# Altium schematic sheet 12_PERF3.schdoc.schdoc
size 302 x 215 mm; Symbol: Sheet_A4; Device: Sheet_A4; @Project Name: Avaota Pi A; Company: YuzukiHD; Version: 1.0; @Page No: 10; @Page Count: 13; @Update Date: 2024-02-27; Comment: GloomyGhost
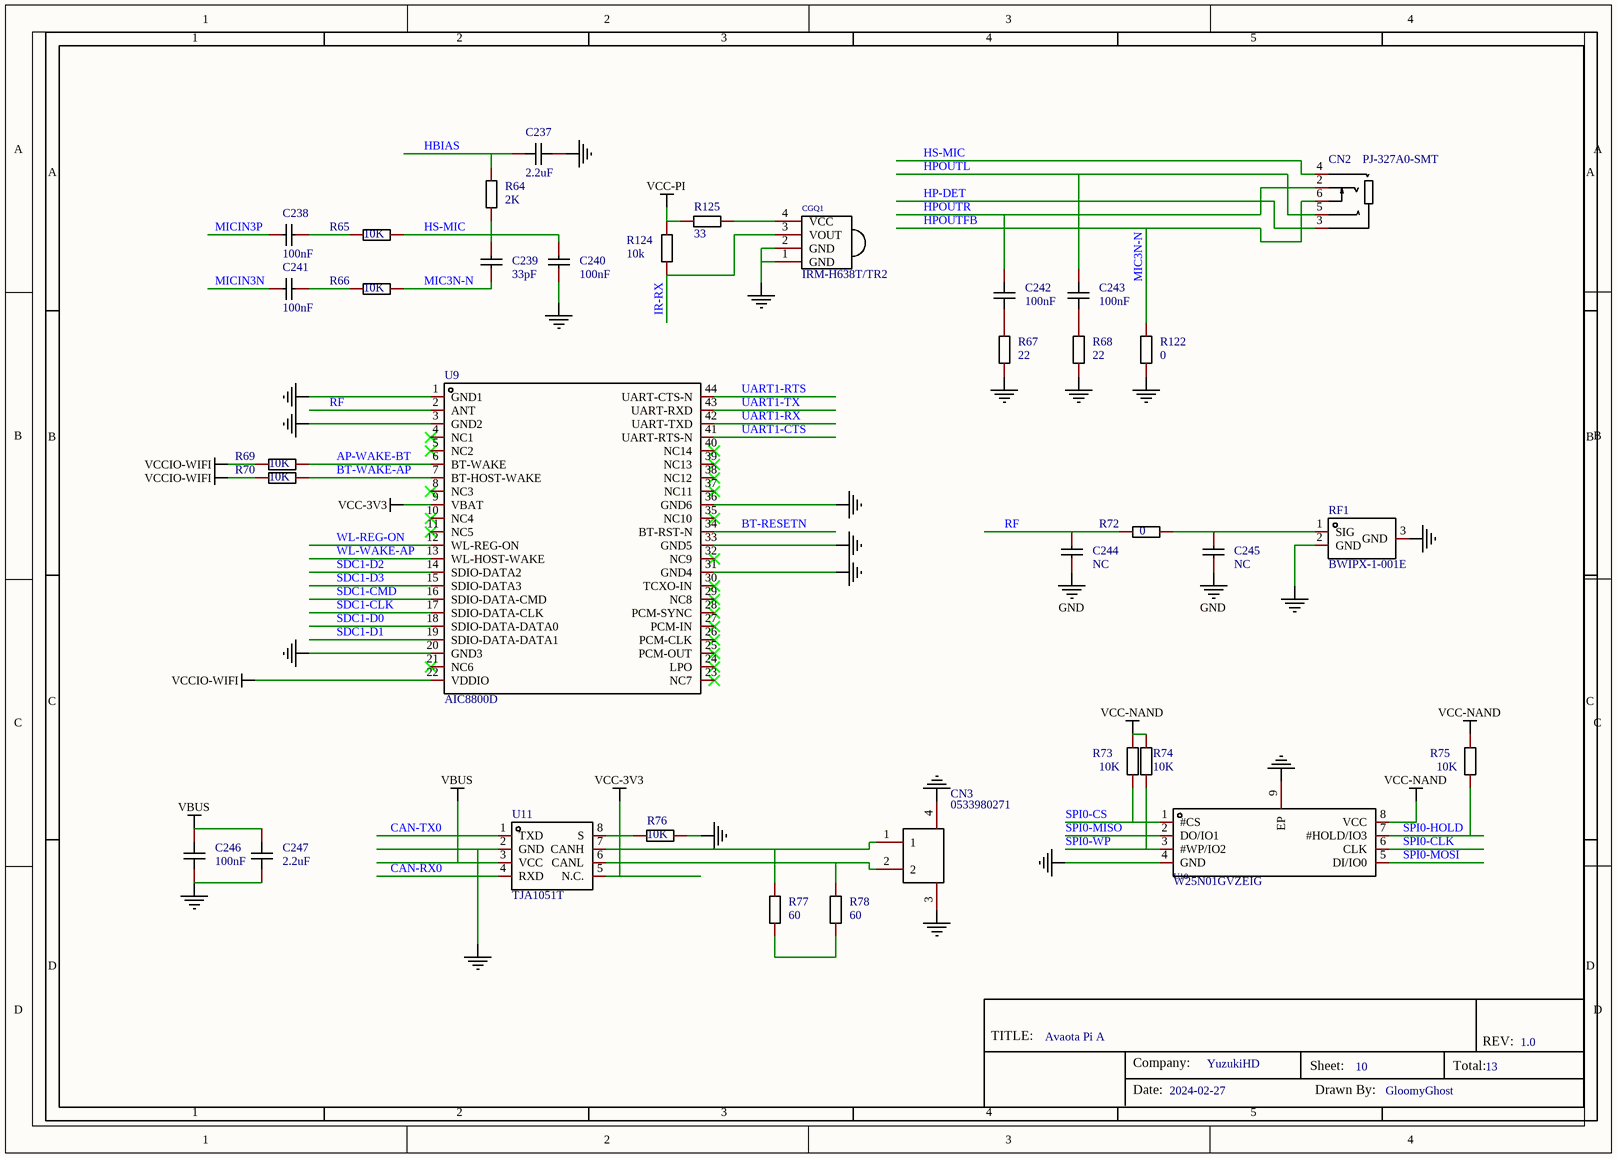
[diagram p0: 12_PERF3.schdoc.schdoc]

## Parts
C237  2.2uF  [c0402-nsk]
C238  100nF  [c0201 nsk]
C239  33pF  [c0201 nsk]
C240  100nF  [c0201 nsk]
C241  100nF  [c0201 nsk]
C242  100nF  [c0402-nsk]
C243  100nF  [c0402-nsk]
C244  NC  [c0201 nsk]
C245  NC  [c0201 nsk]
C246  100nF  [c0402-nsk]
C247  2.2uF  [c0402-nsk]
CGQ1  IRM-H638T/TR2  [SENSOR-SMD_IRM-H638T-TR2-TL]
CN2  PJ-327A0-SMT  [AUDIO-SMD_PJ-327A0-SMT]
CN3  0533980271  [CONN-SMD_2P-P1.25_053398-0X71]
R64  2K  [r0201 nsk]
R65  10K  [r0201 nsk]
R66  10K  [r0201 nsk]
R67  22  [r0201 nsk]
R68  22  [r0201 nsk]
R69  10K  [r0201 nsk]
R70  10K  [r0201 nsk]
R72  0  [r0201 nsk]
R73  10K  [r0201 nsk]
R74  10K  [r0201 nsk]
R75  10K  [r0201 nsk]
R76  10K  [r0201 nsk]
R77  60  [r0201 nsk]
R78  60  [r0201 nsk]
R122  0  [r0201 nsk]
R124  10k  [r0201 nsk]
R125  33  [r0201 nsk]
RF1  BWIPX-1-001E  [IPEX-SMD_BWIPX-1-001E]
U9  AIC8800D  [LGA-44_L12.0-W12.0-P0.90]
U11  TJA1051T  [SOP-8_L4.9-W3.9-P1.27-LS6.0-BL]
U18  W25N01GVZEIG  [WSON-8_L8.0-W6.10-P1.27-BL-EP]

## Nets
GND: C244.1 C245.1 U18.4(GND)
NetC237_1: C237.1 C240.1 C246.1 C247.1 CGQ1.1(GND) CGQ1.2(GND) CN3.3 CN3.4 R67.1 R68.1 R76.2 R122.1 RF1.2(GND) RF1.3(GND) U9.1(GND1) U9.3(GND2) U9.20(GND3) U9.31(GND4) U9.33(GND5) U9.36(GND6) U11.2(GND) U18.9(EP)
VBUS: C246.2 C247.2 U11.3(VCC)
VCC-3V3: U9.9(VBAT) U11.5(N.C.)
VCC-NAND: R73.2 R74.2 R75.2 U18.8(VCC)
VCC-PI: R124.2 R125.2
VCCIO-WIFI: R69.1 R70.1 U9.22(VDDIO)
AP-WAKE-BT: R69.2 U9.6(BT-WAKE)
BT-RESETN: U9.34(BT-RST-N)
BT-WAKE-AP: R70.2 U9.7(BT-HOST-WAKE)
CAN-RX0: U11.4(RXD)
CAN-TX0: U11.1(TXD)
HBIAS: C237.2 R64.2
HP-DET: CN2.3
HPOUTFB: C239.1 CN2.6 R66.2 R122.2  [also labelled MIC3N-N]
HPOUTL: C243.1 CN2.5
HPOUTR: C242.1 CN2.2
HS-MIC: C239.2 C240.2 CN2.4 R64.1 R65.2
IR-RX: CGQ1.3(VOUT) R124.1
MICIN3N: C241.1
MICIN3P: C238.1
RF: C244.2 R72.1 U9.2(ANT)
SDC1-CLK: U9.17(SDIO-DATA-CLK)
SDC1-CMD: U9.16(SDIO-DATA-CMD)
SDC1-D0: U9.18(SDIO-DATA-DATA0)
SDC1-D1: U9.19(SDIO-DATA-DATA1)
SDC1-D2: U9.14(SDIO-DATA2)
SDC1-D3: U9.15(SDIO-DATA3)
SPI0-CLK: U18.6(CLK)
SPI0-CS: R73.1 U18.1(#CS)
SPI0-HOLD: R75.1 U18.7(#HOLD/IO3)
SPI0-MISO: U18.2(DO/IO1)
SPI0-MOSI: U18.5(DI/IO0)
SPI0-WP: R74.1 U18.3(#WP/IO2)
UART1-CTS: U9.41(UART-RTS-N)
UART1-RTS: U9.44(UART-CTS-N)
UART1-RX: U9.42(UART-TXD)
UART1-TX: U9.43(UART-RXD)
WL-REG-ON: U9.12(WL-REG-ON)
WL-WAKE-AP: U9.13(WL-HOST-WAKE)
NetC238_2: C238.2 R65.1
NetC241_2: C241.2 R66.1
NetC242_2: C242.2 R67.2
NetC243_2: C243.2 R68.2
NetC245_2: C245.2 R72.2 RF1.1(SIG)
NetCGQ1_4: CGQ1.4(VCC) R125.1
NetCN3_1: CN3.1 R77.2 U11.7(CANH)
NetCN3_2: CN3.2 R78.2 U11.6(CANL)
NetR76_1: R76.1 U11.8(S)
NetR77_1: R77.1 R78.1

Not connected (* = marked no-connect by the designer): U9 4(NC1)* 5(NC2)* 8(NC3)* 10(NC4)* 11(NC5)* 21(NC6)* 23(NC7)* 24(LPO)* 25(PCM-OUT)* 26(PCM-CLK)* 27(PCM-IN)* 28(PCM-SYNC)* 29(NC8)* 30(TCXO-IN)* 32(NC9)* 35(NC10)* 37(NC11)* 38(NC12)* 39(NC13)* 40(NC14)*

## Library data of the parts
C237 C242 C243 C246 C247 = CAP_0402: Symbol: CapAcitance; Convert to PCB: yes
C238-C241 C244 C245 = GRM033R61A104KE15D: Manufacturer: muRata(村田); Add into BOM: yes; Tolerance: ±10%; Voltage Rated: 10V; Temperature Coefficient: X5R; Description: 容值:100nF;精度:±10%;额定电压:10V;材质(温度系数):X5R;
CGQ1 = IRM-H638T/TR2: Manufacturer: EVERLIGHT(亿光); Add into BOM: yes; Supply Voltage: 2.7V~5.5V; Supply Current: 1.2mA; Description: 工作电压:2.7V~5.5V;工作电流:1.2mA;接收距离:-;中心频率:-;接收角度:-;
CN2 = PJ-327A0-SMT: Manufacturer: XKB Connectivity(中国星坤); Add into BOM: yes; Connector Type: 3.5mm耳机座; Current Rating (Max): 500mA; Voltage Rating (Max): 30V; Soldering Temperature(Max): 235℃; Description: 连接器类型:3.5mm耳机座;额定电流:500mA;额定电压:30V;工作温度范围:-20℃~+70℃;焊接温度(最大值):235℃;
CN3 = 0533980271: Manufacturer: MOLEX; Add into BOM: yes; Pins Structure: 1x2P; Pitch: 1.25mm; Number of PINs Per Row: 2; Description: 插针结构:1x2P;间距:1.25mm;安装方式:立贴;参考系列:-;总PIN数:2P;排数:1;每排PIN数:2;行距:-;额定电流:-;触头材质:磷青铜;触头镀层:锡;工作温度范围:-;
R64-R70 R72-R78 R122 R124 R125 = Res_0201: Symbol: 电阻; Convert to PCB: yes
RF1 = BWIPX-1-001E: Manufacturer: BAT WIRELESS(蝙蝠无线); Add into BOM: yes; Connector Type: 板端; Interface Type: 内针; Frequency-Max: 6GHz; RF Series: IPEX; Number of Ports: 1; Impedance: 50Ω; Description: 连接器类型:板端;接口类型:内针;频率-最大值:6GHz;接口直径:-;射频系列:IPEX;端口数量:1;阻抗:50Ω;样式:-;接口长度/高度:-;工作温度范围:-;
U9 = XR829MQ: Add into BOM: yes
U11 = TJA1051T_C7432801: Manufacturer: Tokmas(托克马斯); Add into BOM: yes; Data Rate: 5Mbps; Description: 类型:收发器;数据速率:5Mbps;
U18 = W25N01GVZEIG_C88868: Manufacturer: WINBOND(华邦); Add into BOM: yes; Description: 1-Gbit(128M x 8bit)，SPI接口，工作电压：2.7V to 3.6V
